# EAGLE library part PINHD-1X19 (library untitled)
PIN HEADER
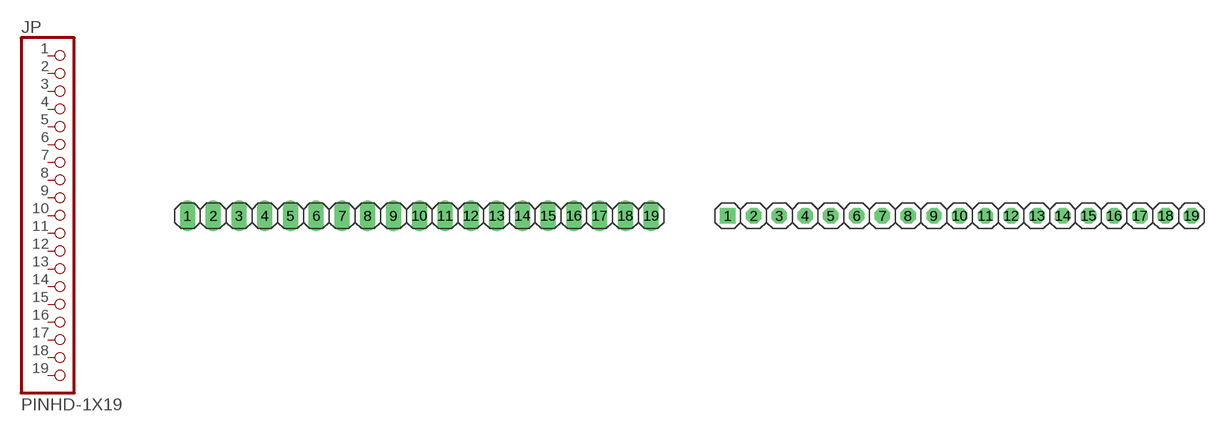
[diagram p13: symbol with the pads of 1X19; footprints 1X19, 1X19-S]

Designator prefix JP

## PINHD-1X19_2.54  [1X19]
1  1  pas
2  2  pas
3  3  pas
4  4  pas
5  5  pas
6  6  pas
7  7  pas
8  8  pas
9  9  pas
10  10  pas
11  11  pas
12  12  pas
13  13  pas
14  14  pas
15  15  pas
16  16  pas
17  17  pas
18  18  pas
19  19  pas

## PINHD-1X19_2.54-S  [1X19-S]
Pads as for 1X19

## PINHD-1X19_2.54-90°  [1X19/90]
Pads as for 1X19

## PINHD-1X19_2.54-90°-S  [1X19/90-S]
Pads as for 1X19

## PINHD-1X19_2.00  [1X19M]
Pads as for 1X19

## PINHD-1X19_2.54-SMD  [1X19SMD]
Pads as for 1X19

## PINHD-1X19  [1X19SMD/90]
Pads as for 1X19

## Footprint 1X19 (pad centres in mm)
PIN HEADER - 2.54
drill 1.016 long: 1 -22.86,0; 2 -20.32,0; 3 -17.78,0; 4 -15.24,0; 5 -12.7,0; 6 -10.16,0; 7 -7.62,0; 8 -5.08,0; 9 -2.54,0; 10 0,0; 11 2.54,0; 12 5.08,0; 13 7.62,0; 14 10.16,0; 15 12.7,0; 16 15.24,0; 17 17.78,0; 18 20.32,0; 19 22.86,0

## Footprint 1X19-S (pad centres in mm)
PIN HEADER - 2.54
drill 1.016 square: 1 -22.86,0
drill 1.016 octagon: 2 -20.32,0; 3 -17.78,0; 4 -15.24,0; 5 -12.7,0; 6 -10.16,0; 7 -7.62,0; 8 -5.08,0; 9 -2.54,0; 10 0,0; 11 2.54,0; 12 5.08,0; 13 7.62,0; 14 10.16,0; 15 12.7,0; 16 15.24,0; 17 17.78,0; 18 20.32,0; 19 22.86,0

## Footprint 1X19/90 (pad centres in mm)
PIN HEADER - 2.54 90°
drill 1.016 long: 1 -22.86,-3.81; 2 -20.32,-3.81; 3 -17.78,-3.81; 4 -15.24,-3.81; 5 -12.7,-3.81; 6 -10.16,-3.81; 7 -7.62,-3.81; 8 -5.08,-3.81; 9 -2.54,-3.81; 10 0,-3.81; 11 2.54,-3.81; 12 5.08,-3.81; 13 7.62,-3.81; 14 10.16,-3.81; 15 12.7,-3.81; 16 15.24,-3.81; 17 17.78,-3.81; 18 20.32,-3.81; 19 22.86,-3.81

## Footprint 1X19/90-S (pad centres in mm)
PIN HEADER - 2.54 90°
drill 1.016 square: 1 -22.86,-3.81
drill 1.016 octagon: 2 -20.32,-3.81; 3 -17.78,-3.81; 4 -15.24,-3.81; 5 -12.7,-3.81; 6 -10.16,-3.81; 7 -7.62,-3.81; 8 -5.08,-3.81; 9 -2.54,-3.81; 10 0,-3.81; 11 2.54,-3.81; 12 5.08,-3.81; 13 7.62,-3.81; 14 10.16,-3.81; 15 12.7,-3.81; 16 15.24,-3.81; 17 17.78,-3.81; 18 20.32,-3.81; 19 22.86,-3.81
